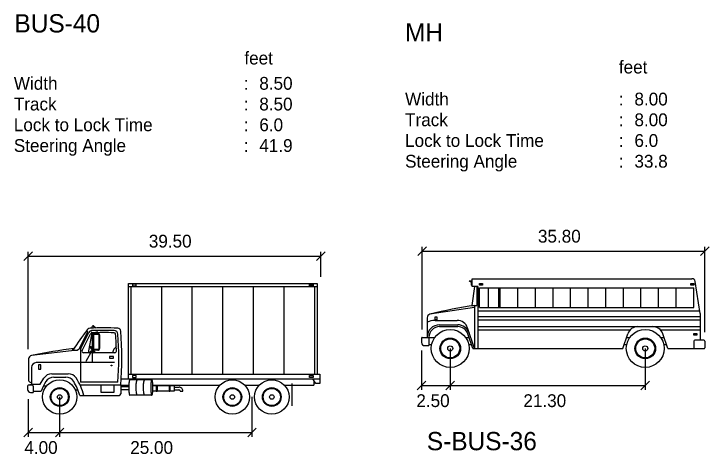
# Model space of a CAD drawing. Extents: x 2297881 to 2300600, y 559917 to 564426.
# Drawn here: x 2299073.1 to 2299144.5, y 562642 to 562687.1 of the extents above; entities that cross this region are included whole.
import ezdxf

# ---------------------------------------------------------------- set-up
doc = ezdxf.new("R2010")
doc.units = 0
doc.layers.add('DR_X_Elev_Flow', color=7, linetype='Continuous')

msp = doc.modelspace()

# ---------------------------------------------------------------- linework, layer by layer
at = {"layer": 'DR_X_Elev_Flow'}
for p, q in [((2299115.476, 562663.249), (2299114.591, 562662.363)), ((2299115.033, 562654.796), (2299115.033, 562663.249)), ((2299115.033, 562662.806), (2299144.02, 562662.806)), ((2299144.463, 562663.249), (2299143.577, 562662.363)), ((2299144.02, 562654.496), (2299144.02, 562663.249)), ((2299075.027, 562662.743), (2299074.141, 562661.858)), ((2299074.584, 562652.777), (2299074.584, 562662.743)), ((2299074.584, 562662.301), (2299104.618, 562662.301)), ((2299105.061, 562662.743), (2299104.175, 562661.858)), ((2299104.618, 562660.183), (2299104.618, 562662.743)), ((2299120.159, 562659.992), (2299142.707, 562659.992)), ((2299120.159, 562659.176), (2299120.159, 562659.992)), ((2299084.881, 562649.712), (2299084.881, 562659.487)), ((2299084.881, 562659.487), (2299104.266, 562659.487)), ((2299084.881, 562659.206), (2299104.266, 562659.206)), ((2299085.161, 562650.198), (2299085.161, 562659.206)), ((2299085.696, 562659.436), (2299085.292, 562659.436)), ((2299085.292, 562659.436), (2299085.292, 562659.256)), ((2299085.292, 562659.256), (2299085.696, 562659.256)), ((2299085.696, 562659.256), (2299085.696, 562659.436)), ((2299088.299, 562650.198), (2299088.299, 562659.206)), ((2299091.436, 562650.198), (2299091.436, 562659.206)), ((2299094.573, 562650.198), (2299094.573, 562659.206)), ((2299097.711, 562650.198), (2299097.711, 562659.206)), ((2299100.848, 562650.198), (2299100.848, 562659.206)), ((2299103.45, 562659.256), (2299103.45, 562659.436)), ((2299103.45, 562659.436), (2299103.855, 562659.436)), ((2299103.855, 562659.256), (2299103.45, 562659.256)), ((2299103.855, 562659.436), (2299103.855, 562659.256)), ((2299103.985, 562659.206), (2299103.985, 562650.198)), ((2299104.266, 562659.487), (2299104.266, 562650.198)), ((2299119.856, 562659.757), (2299120.159, 562659.757)), ((2299119.956, 562659.703), (2299119.913, 562659.714)), ((2299120.095, 562659.339), (2299120.095, 562659.524)), ((2299120.141, 562659.293), (2299120.159, 562659.293)), ((2299120.916, 562659.508), (2299121.205, 562659.508)), ((2299120.916, 562659.328), (2299120.916, 562659.508)), ((2299121.205, 562659.328), (2299120.916, 562659.328)), ((2299121.205, 562659.508), (2299121.205, 562659.328)), ((2299142.602, 562659.328), (2299142.602, 562659.508)), ((2299142.602, 562659.508), (2299142.89, 562659.508)), ((2299142.89, 562659.328), (2299142.602, 562659.328)), ((2299142.89, 562659.508), (2299142.89, 562659.328)), ((2299143.547, 562656.438), (2299143.031, 562659.715)), ((2299120.741, 562659.176), (2299120.159, 562659.176)), ((2299120.165, 562657.251), (2299120.43, 562659.176)), ((2299120.649, 562659.176), (2299120.649, 562657.251)), ((2299120.741, 562659.176), (2299120.741, 562652.828)), ((2299120.916, 562659.063), (2299142.89, 562659.063)), ((2299120.916, 562657.04), (2299120.916, 562659.063)), ((2299121.846, 562657.04), (2299121.846, 562659.063)), ((2299122.885, 562657.04), (2299122.885, 562659.063)), ((2299123.035, 562657.04), (2299123.035, 562659.063)), ((2299124.84, 562657.04), (2299124.84, 562659.063)), ((2299126.645, 562657.04), (2299126.645, 562659.063)), ((2299128.45, 562657.04), (2299128.45, 562659.063)), ((2299130.255, 562657.04), (2299130.255, 562659.063)), ((2299132.06, 562657.04), (2299132.06, 562659.063)), ((2299133.865, 562657.04), (2299133.865, 562659.063)), ((2299135.67, 562657.04), (2299135.67, 562659.063)), ((2299137.475, 562657.04), (2299137.475, 562659.063)), ((2299139.28, 562657.04), (2299139.28, 562659.063)), ((2299141.085, 562657.04), (2299141.085, 562659.063)), ((2299142.89, 562657.04), (2299142.89, 562659.063)), ((2299120.165, 562657.251), (2299120.649, 562657.251)), ((2299120.407, 562657.251), (2299120.407, 562652.828)), ((2299120.407, 562657.035), (2299115.824, 562656.352)), ((2299120.741, 562656.712), (2299143.504, 562656.712)), ((2299120.916, 562657.04), (2299142.89, 562657.04)), ((2299143.547, 562656.438), (2299143.547, 562653.676)), ((2299115.535, 562655.989), (2299115.535, 562653.975)), ((2299116.341, 562655.781), (2299116.341, 562656.069)), ((2299116.341, 562656.069), (2299116.521, 562656.069)), ((2299116.521, 562655.781), (2299116.341, 562655.781)), ((2299116.341, 562655.716), (2299118.603, 562655.716)), ((2299116.521, 562656.069), (2299116.521, 562655.781)), ((2299120.741, 562656.11), (2299143.547, 562656.11)), ((2299120.741, 562655.782), (2299143.547, 562655.782)), ((2299081.318, 562655.152), (2299081.551, 562654.941)), ((2299081.318, 562655.152), (2299081.326, 562654.933)), ((2299116.805, 562655.263), (2299118.669, 562655.263)), ((2299116.805, 562655.076), (2299118.669, 562655.076)), ((2299120.408, 562652.828), (2299119.69, 562654.938)), ((2299120.741, 562655.076), (2299143.547, 562655.076)), ((2299079.844, 562652.808), (2299080.692, 562654.489)), ((2299079.998, 562652.824), (2299080.835, 562654.491)), ((2299080.133, 562652.64), (2299081.007, 562654.355)), ((2299080.631, 562654.728), (2299080.642, 562654.71)), ((2299080.702, 562654.568), (2299080.642, 562654.71)), ((2299081.142, 562654.443), (2299080.748, 562652.404)), ((2299081.073, 562654.581), (2299081.165, 562654.386)), ((2299081.165, 562654.386), (2299081.751, 562654.581)), ((2299081.165, 562654.386), (2299081.762, 562654.386)), ((2299081.165, 562654.386), (2299081.165, 562651.504)), ((2299081.338, 562652.744), (2299081.338, 562654.305)), ((2299081.338, 562654.305), (2299081.843, 562654.305)), ((2299081.59, 562654.305), (2299081.59, 562654.386)), ((2299081.843, 562654.305), (2299081.843, 562652.744)), ((2299081.924, 562654.224), (2299081.924, 562652.825)), ((2299120.21, 562652.828), (2299119.694, 562654.342)), ((2299120.741, 562654.748), (2299136.37, 562654.748)), ((2299135.606, 562652.828), (2299136.122, 562654.342)), ((2299139.456, 562654.748), (2299143.547, 562654.748)), ((2299140.22, 562652.828), (2299139.704, 562654.342)), ((2299142.911, 562654.21), (2299142.911, 562654.39)), ((2299142.911, 562654.39), (2299143.199, 562654.39)), ((2299143.199, 562654.21), (2299142.911, 562654.21)), ((2299143.199, 562654.39), (2299143.199, 562654.21)), ((2299114.953, 562653.894), (2299114.953, 562653.451)), ((2299115.033, 562653.975), (2299116.321, 562653.975)), ((2299115.722, 562653.975), (2299115.722, 562653.127)), ((2299119.485, 562653.975), (2299119.819, 562653.975)), ((2299135.997, 562653.975), (2299136.331, 562653.975)), ((2299139.495, 562653.975), (2299139.829, 562653.975)), ((2299142.911, 562653.594), (2299142.911, 562652.91)), ((2299143.938, 562653.676), (2299142.993, 562653.676)), ((2299144.02, 562653.594), (2299144.02, 562652.91)), ((2299081.405, 562652.404), (2299080.983, 562652.941)), ((2299081.507, 562652.404), (2299081.045, 562652.991)), ((2299115.276, 562653.127), (2299115.722, 562653.127)), ((2299115.722, 562653.25), (2299116.001, 562653.25)), ((2299117.903, 562652.844), (2299117.903, 562648.588)), ((2299119.805, 562653.25), (2299120.066, 562653.25)), ((2299120.21, 562652.828), (2299135.606, 562652.828)), ((2299135.75, 562653.25), (2299136.011, 562653.25)), ((2299137.913, 562652.844), (2299137.913, 562648.588)), ((2299139.815, 562653.25), (2299140.076, 562653.25)), ((2299140.22, 562652.828), (2299142.993, 562652.828)), ((2299142.993, 562652.828), (2299143.938, 562652.828)), ((2299079.609, 562652.678), (2299074.941, 562652.13)), ((2299079.964, 562652.679), (2299079.964, 562649.385)), ((2299083.491, 562652.404), (2299080.277, 562652.404)), ((2299081.165, 562652.663), (2299080.526, 562651.504)), ((2299080.824, 562652.404), (2299081.183, 562652.687)), ((2299081.762, 562652.663), (2299081.165, 562652.663)), ((2299081.276, 562652.404), (2299081.356, 562652.467)), ((2299081.843, 562652.744), (2299081.338, 562652.744)), ((2299081.59, 562652.744), (2299081.59, 562652.663)), ((2299114.953, 562652.631), (2299114.953, 562648.588)), ((2299074.647, 562651.766), (2299074.647, 562649.564)), ((2299083.473, 562651.387), (2299075.427, 562651.387)), ((2299082.939, 562652.024), (2299082.939, 562651.844)), ((2299083.344, 562652.024), (2299082.939, 562652.024)), ((2299082.939, 562651.844), (2299083.344, 562651.844)), ((2299083.344, 562651.844), (2299083.344, 562652.024)), ((2299074.941, 562650.901), (2299074.941, 562649.355)), ((2299075.889, 562651.148), (2299075.672, 562651.148)), ((2299075.672, 562651.148), (2299075.672, 562650.705)), ((2299075.672, 562650.705), (2299075.889, 562650.705)), ((2299075.889, 562650.705), (2299075.889, 562651.148)), ((2299077.033, 562650.245), (2299078.708, 562650.245)), ((2299084.881, 562650.198), (2299104.526, 562650.198)), ((2299085.292, 562650.053), (2299085.292, 562649.873)), ((2299085.696, 562650.053), (2299085.292, 562650.053)), ((2299085.696, 562649.873), (2299085.696, 562650.053)), ((2299103.45, 562650.053), (2299103.855, 562650.053)), ((2299103.45, 562649.873), (2299103.45, 562650.053)), ((2299103.855, 562650.053), (2299103.855, 562649.873)), ((2299104.526, 562650.198), (2299104.526, 562649.241)), ((2299074.941, 562649.32), (2299074.941, 562649.201)), ((2299075.824, 562649.172), (2299076.209, 562649.788)), ((2299077.228, 562649.893), (2299078.46, 562649.893)), ((2299083.8, 562649.385), (2299079.964, 562649.385)), ((2299084.144, 562649.712), (2299084.881, 562649.712)), ((2299084.881, 562649.712), (2299104.526, 562649.712)), ((2299087.282, 562649.626), (2299085.028, 562649.626)), ((2299085.292, 562649.873), (2299085.696, 562649.873)), ((2299101.664, 562649.245), (2299101.664, 562646.944)), ((2299103.855, 562649.873), (2299103.45, 562649.873)), ((2299104.108, 562649.241), (2299103.796, 562649.712)), ((2299103.895, 562649.564), (2299103.895, 562649.069)), ((2299104.526, 562649.241), (2299104.108, 562649.241)), ((2299115.395, 562649.473), (2299114.51, 562648.588)), ((2299118.346, 562649.473), (2299117.46, 562648.588)), ((2299138.356, 562649.473), (2299137.47, 562648.588)), ((2299074.526, 562648.986), (2299074.526, 562648.648)), ((2299074.607, 562649.067), (2299074.914, 562649.164)), ((2299075.039, 562649.067), (2299074.607, 562649.067)), ((2299074.941, 562649.172), (2299075.824, 562649.172)), ((2299075.12, 562648.986), (2299075.12, 562648.324)), ((2299076.449, 562648.963), (2299076.145, 562648.963)), ((2299079.451, 562648.596), (2299079.703, 562648.596)), ((2299084.097, 562649.069), (2299079.952, 562649.069)), ((2299082.085, 562648.313), (2299082.085, 562649.069)), ((2299083.389, 562649.069), (2299083.389, 562648.313)), ((2299084.097, 562649.069), (2299084.92, 562649.069)), ((2299084.097, 562649.069), (2299084.097, 562648.186)), ((2299084.916, 562648.919), (2299084.097, 562648.919)), ((2299084.921, 562648.596), (2299084.097, 562648.596)), ((2299087.39, 562649.069), (2299094.253, 562649.069)), ((2299087.747, 562649.014), (2299087.392, 562649.014)), ((2299087.747, 562649.069), (2299087.747, 562648.413)), ((2299087.825, 562649.069), (2299087.825, 562648.413)), ((2299089.061, 562649.014), (2299087.825, 562649.014)), ((2299089.061, 562649.069), (2299089.061, 562648.413)), ((2299089.139, 562649.069), (2299089.139, 562648.413)), ((2299089.58, 562649.014), (2299089.139, 562649.014)), ((2299089.58, 562649.014), (2299089.58, 562648.468)), ((2299089.58, 562648.874), (2299090.074, 562648.874)), ((2299089.58, 562648.608), (2299090.073, 562648.608)), ((2299096.84, 562649.069), (2299098.302, 562649.069)), ((2299100.888, 562649.069), (2299103.895, 562649.069)), ((2299114.953, 562649.03), (2299137.913, 562649.03)), ((2299074.849, 562648.324), (2299075.12, 562648.324)), ((2299075.12, 562648.446), (2299075.921, 562648.446)), ((2299077.83, 562647.864), (2299077.83, 562643.784)), ((2299079.888, 562648.024), (2299083.935, 562648.024)), ((2299083.389, 562648.313), (2299082.085, 562648.313)), ((2299087.282, 562648.062), (2299085.028, 562648.062)), ((2299087.747, 562648.468), (2299087.381, 562648.468)), ((2299087.825, 562648.413), (2299087.747, 562648.413)), ((2299089.061, 562648.468), (2299087.825, 562648.468)), ((2299089.139, 562648.413), (2299089.061, 562648.413)), ((2299089.58, 562648.468), (2299089.139, 562648.468)), ((2299090.209, 562648.472), (2299090.476, 562648.472)), ((2299097.563, 562647.864), (2299097.563, 562643.784)), ((2299074.584, 562647.638), (2299074.584, 562643.784)), ((2299075.027, 562644.67), (2299074.141, 562643.784)), ((2299074.584, 562644.227), (2299097.563, 562644.227)), ((2299078.273, 562644.67), (2299077.387, 562643.784)), ((2299098.005, 562644.67), (2299097.12, 562643.784))]:
    msp.add_line(p, q, dxfattribs=at)
for centre, radius in [((2299117.903, 562652.844), 1.945), ((2299137.913, 562652.844), 1.945), ((2299117.903, 562652.844), 1.059), ((2299117.903, 562652.844), 0.971), ((2299137.913, 562652.844), 1.059), ((2299137.913, 562652.844), 0.971), ((2299117.903, 562652.844), 0.254), ((2299137.913, 562652.844), 0.254), ((2299083.142, 562651.097), 0.0389), ((2299077.834, 562647.864), 1.768), ((2299095.546, 562647.864), 1.768), ((2299099.595, 562647.864), 1.768), ((2299077.834, 562647.864), 0.963), ((2299077.834, 562647.864), 0.883), ((2299095.546, 562647.864), 0.963), ((2299095.546, 562647.864), 0.883), ((2299099.595, 562647.864), 0.963), ((2299099.595, 562647.864), 0.883), ((2299077.834, 562647.864), 0.231), ((2299095.546, 562647.864), 0.231), ((2299099.595, 562647.864), 0.231)]:
    msp.add_circle(centre, radius, dxfattribs=at)
for centre, radius, start, end in [((2299142.707, 562659.664), 0.328, 8.94405, 90), ((2299119.936, 562659.803), 0.0923, 210.12886, 255.60187), ((2299119.91, 562659.524), 0.185, 0, 75.60187), ((2299120.227, 562659.525), 0.193, 147.93199, 226.86625), ((2299120.141, 562659.339), 0.0461, 180, 270), ((2299126.945, 562611.801), 45.918, 98.18652, 104.01654), ((2299115.907, 562655.989), 0.372, 102.87377, 180), ((2299116.341, 562653.805), 1.911, 90, 114.94146), ((2299118.603, 562654.568), 1.148, 18.79424, 90), ((2299080.947, 562654.592), 0.324, 90, 134.17879), ((2299082.36, 562623.559), 31.389, 87.39503, 92.58011), ((2299081.267, 562655.009), 0.152, 70.46127, 213.19655), ((2299116.805, 562653.993), 1.27, 90, 180), ((2299116.805, 562653.993), 1.083, 90, 180), ((2299118.669, 562653.993), 1.27, 18.79424, 90), ((2299118.669, 562653.993), 1.083, 18.79424, 90), ((2299137.147, 562653.993), 1.083, 90, 161.20576), ((2299138.679, 562653.993), 1.083, 18.79424, 90), ((2299095.641, 562642.555), 19.307, 140.97949, 148.30163), ((2299096.397, 562639.889), 21.651, 136.38577, 136.73563), ((2299080.627, 562654.537), 0.0809, 323.5286, 22.79817), ((2299081.125, 562654.345), 0.324, 92.07415, 153.32848), ((2299081.152, 562654.282), 0.162, 91.97433, 152.99145), ((2299082.396, 562619.227), 35.466, 88.33779, 92.07415), ((2299082.391, 562618.33), 36.135, 88.3779, 91.97433), ((2299081.762, 562654.224), 0.162, 359.99996, 90.00004), ((2299083.408, 562654.289), 0.162, 4.26303, 87.7744), ((2299083.41, 562654.289), 0.389, 4.29297, 87.7406), ((2299050.432, 562651.831), 33.229, 1.27474, 4.26303), ((2299083.772, 562654.592), 0.324, 4.81346, 87.39503), ((2299050.661, 562651.831), 33.229, 355.77901, 4.29297), ((2299050.983, 562651.831), 33.229, 355.23306, 4.81346), ((2299115.033, 562653.894), 0.0809, 90, 180), ((2299142.993, 562653.594), 0.082, 90, 180), ((2299143.938, 562653.594), 0.082, 0, 90), ((2299088.965, 562580.604), 72.889, 97.6136, 101.09313), ((2299079.176, 562652.753), 0.0347, 126.00051, 185.11623), ((2299079.383, 562652.467), 0.388, 109.03096, 126.00045), ((2299079.548, 562651.989), 0.894, 105.56756, 109.03094), ((2299079.583, 562653.001), 0.324, 274.5808, 323.5286), ((2299080.288, 562652.679), 0.324, 153.32848, 180), ((2299081.014, 562652.966), 0.0398, 38.21195, 218.21195), ((2299081.762, 562652.825), 0.162, 269.99996, 0.00004), ((2299084.591, 562652.035), 1.394, 133.12336, 164.62333), ((2299115.276, 562653.451), 0.324, 180, 270), ((2299142.993, 562652.91), 0.082, 180, 270), ((2299143.938, 562652.91), 0.082, 270, 360), ((2299075.02, 562651.766), 0.372, 102.87377, 180), ((2299079.215, 562652.792), 0.0853, 209.8358, 247.28746), ((2299079.351, 562653.063), 0.388, 244.23208, 261.20157), ((2299079.428, 562653.563), 0.894, 261.20161, 269.25706), ((2299079.438, 562654.357), 1.688, 269.25709, 275.11625), ((2299079.438, 562654.357), 1.688, 275.11621, 275.84822), ((2299080.277, 562652.566), 0.162, 152.99145, 270), ((2299083.491, 562652.566), 0.162, 270, 1.27474), ((2299075.427, 562650.901), 0.486, 90, 180), ((2299077.033, 562649.274), 0.971, 90, 147.99462), ((2299078.708, 562649.274), 0.971, 33.72618, 90), ((2299074.809, 562649.564), 0.162, 180, 242.78303), ((2299074.987, 562649.855), 0.503, 239.9001, 260.98766), ((2299074.902, 562649.32), 0.0389, 0, 80.98766), ((2299081.528, 562646.325), 5.995, 148.73173, 159.27429), ((2299077.228, 562648.922), 0.971, 90, 147.99462), ((2299078.46, 562648.922), 0.971, 33.69007, 90), ((2299074.862, 562646.706), 5.196, 14.69606, 32.0084), ((2299074.862, 562646.706), 5.596, 13.62639, 33.72618), ((2299087.68, 562649.003), 2.76, 171.78138, 176.57634), ((2299086.056, 562649.237), 1.119, 160.77672, 171.78142), ((2299085.028, 562649.596), 0.0307, 89.99998, 160.77674), ((2299088.415, 562649.003), 2.76, 171.78138, 176.57634), ((2299086.79, 562649.237), 1.119, 160.77672, 171.78142), ((2299085.763, 562649.596), 0.0307, 89.99998, 160.77675), ((2299089.166, 562649.003), 2.76, 171.78138, 176.57634), ((2299087.541, 562649.237), 1.119, 160.77672, 171.78142), ((2299086.514, 562649.596), 0.0307, 89.99998, 160.77674), ((2299089.934, 562649.003), 2.76, 171.78138, 176.57634), ((2299088.309, 562649.237), 1.119, 160.77672, 171.78142), ((2299087.282, 562649.596), 0.0307, 89.99998, 160.77675), ((2299087.282, 562649.596), 0.0307, 19.22326, 90.00002), ((2299086.254, 562649.237), 1.119, 8.21858, 19.22328), ((2299084.63, 562649.003), 2.76, 3.42366, 8.21862), ((2299074.607, 562648.986), 0.0809, 90, 180), ((2299074.849, 562648.648), 0.324, 180, 270), ((2299074.902, 562649.201), 0.0389, 287.39741, 0), ((2299075.039, 562648.986), 0.0809, 0, 90), ((2299090.327, 562648.844), 5.412, 176.57628, 180.00002), ((2299090.327, 562648.844), 5.412, 179.99998, 183.42372), ((2299087.68, 562648.686), 2.76, 183.42366, 188.21862), ((2299091.062, 562648.844), 5.412, 176.57628, 180.00002), ((2299091.062, 562648.844), 5.412, 179.99998, 183.42372), ((2299088.415, 562648.686), 2.76, 183.42366, 188.21862), ((2299091.813, 562648.844), 5.412, 176.57628, 180.00002), ((2299091.813, 562648.844), 5.412, 179.99998, 183.42372), ((2299089.166, 562648.686), 2.76, 183.42366, 188.21862), ((2299092.581, 562648.844), 5.412, 176.57628, 180.00002), ((2299092.581, 562648.844), 5.412, 179.99998, 183.42372), ((2299089.934, 562648.686), 2.76, 183.42366, 188.21862), ((2299084.63, 562648.686), 2.76, 351.78138, 356.57634), ((2299081.983, 562648.844), 5.412, 359.99998, 3.42372), ((2299081.983, 562648.844), 5.412, 356.57628, 0.00002), ((2299090.073, 562648.472), 0.136, 0, 90), ((2299090.074, 562648.473), 0.401, 359.83304, 90), ((2299083.935, 562648.186), 0.162, 270, 0), ((2299086.056, 562648.451), 1.119, 188.21858, 199.22328), ((2299085.028, 562648.093), 0.0307, 199.22326, 270.00002), ((2299086.79, 562648.451), 1.119, 188.21858, 199.22328), ((2299085.763, 562648.093), 0.0307, 199.22325, 270.00002), ((2299087.541, 562648.451), 1.119, 188.21858, 199.22328), ((2299086.514, 562648.093), 0.0307, 199.22326, 270.00002), ((2299088.309, 562648.451), 1.119, 188.21858, 199.22328), ((2299087.282, 562648.093), 0.0307, 199.22325, 270.00002), ((2299087.282, 562648.093), 0.0307, 269.99998, 340.77674), ((2299086.254, 562648.451), 1.119, 340.77672, 351.78142)]:
    msp.add_arc(centre, radius, start, end, dxfattribs=at)

# ---------------------------------------------------------------- texts
for s, height, p in [('BUS-40', 1.8748, (2299073.191, 562685.236)), ('MH', 1.8748, (2299113.271, 562684.314)), ('feet', 1.3123, (2299096.783, 562681.955)), ('feet', 1.3123, (2299135.207, 562681.033)), ('Width', 1.3123, (2299073.127, 562679.365)), ('8.50', 1.3123, (2299098.314, 562679.365)), (':', 1.312, (2299096.719, 562679.365)), ('Track', 1.3123, (2299073.127, 562677.24)), ('8.50', 1.3123, (2299098.314, 562677.24)), ('Width', 1.3123, (2299113.271, 562677.752)), (':', 1.312, (2299135.207, 562677.752)), ('8.00', 1.3123, (2299136.802, 562677.752)), (':', 1.312, (2299096.719, 562677.24)), ('Lock to Lock Time', 1.31234, (2299073.127, 562675.115)), ('6.0', 1.3123, (2299098.314, 562675.115)), ('Track', 1.3123, (2299113.271, 562675.628)), (':', 1.312, (2299135.207, 562675.628)), ('8.00', 1.3123, (2299136.802, 562675.628)), (':', 1.312, (2299096.719, 562675.115)), ('Steering Angle', 1.31234, (2299073.127, 562672.99)), ('41.9', 1.3123, (2299098.314, 562672.99)), ('Lock to Lock Time', 1.31234, (2299113.271, 562673.503)), (':', 1.312, (2299135.207, 562673.503)), ('6.0', 1.3123, (2299136.802, 562673.503)), (':', 1.312, (2299096.719, 562672.99)), ('Steering Angle', 1.31234, (2299113.271, 562671.378)), (':', 1.312, (2299135.207, 562671.378)), ('33.8', 1.3123, (2299136.802, 562671.378)), ('35.80', 1.3123, (2299126.902, 562663.692)), ('39.50', 1.3123, (2299086.977, 562663.186)), ('2.50', 1.3123, (2299114.428, 562646.832)), ('21.30', 1.3123, (2299125.408, 562646.832)), ('S-BUS-36', 1.8748, (2299115.504, 562642.403)), ('4.00', 1.3123, (2299074.207, 562642.029)), ('25.00', 1.3123, (2299085.071, 562642.029))]:
    msp.add_text(s, height=height, dxfattribs=at).set_placement(p)

doc.saveas('drawing.dxf')
